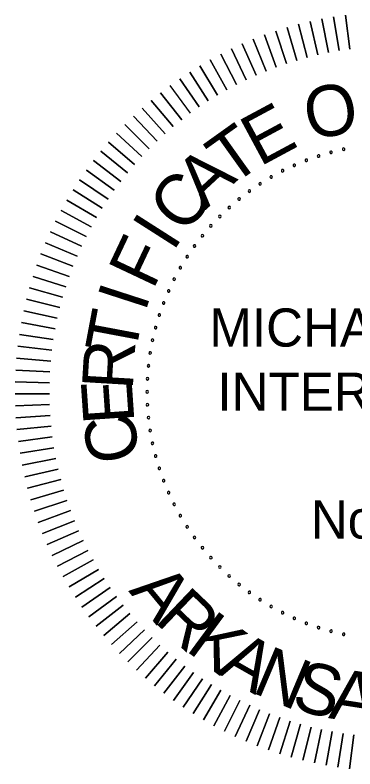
# Model space of a CAD drawing. Extents: x -4306 to 3843, y 131 to 8053.
# Drawn here: x 2723.6 to 2834.9, y 323.4 to 570.4 of the extents above; entities that cross this region are included whole.
import ezdxf

# ---------------------------------------------------------------- set-up
doc = ezdxf.new("R2010")
doc.units = 0
doc.layers.add('G-ANNO-TEXT', color=7, linetype='Continuous')

msp = doc.modelspace()

# ---------------------------------------------------------------- linework, layer by layer
at = {"layer": 'G-ANNO-TEXT'}
for points in [[(2822.74, 557.35), (2820.23, 568.28)], [(2820.23, 568.28), (2822.74, 557.35)], [(2826.22, 558.09), (2824.06, 569.1)], [(2824.06, 569.1), (2826.22, 558.09)], [(2829.72, 558.72), (2827.9, 569.79)], [(2827.9, 569.79), (2829.72, 558.72)], [(2833.24, 559.24), (2831.77, 570.36)], [(2831.77, 570.36), (2833.24, 559.24)], [(2815.86, 555.54), (2812.67, 566.3)], [(2812.67, 566.3), (2815.86, 555.54)], [(2819.29, 556.5), (2816.44, 567.35)], [(2816.44, 567.35), (2819.29, 556.5)], [(2809.11, 553.3), (2805.25, 563.84)], [(2805.25, 563.84), (2809.11, 553.3)], [(2812.47, 554.47), (2808.94, 565.13)], [(2808.94, 565.13), (2812.47, 554.47)], [(2802.51, 550.65), (2798, 560.92)], [(2798, 560.92), (2802.51, 550.65)], [(2805.79, 552.03), (2801.6, 562.44)], [(2801.6, 562.44), (2805.79, 552.03)], [(2799.28, 549.17), (2794.44, 559.29)], [(2794.44, 559.29), (2799.28, 549.17)], [(2792.96, 545.9), (2787.5, 555.71)], [(2787.5, 555.71), (2792.96, 545.9)], [(2796.09, 547.58), (2790.94, 557.55)], [(2790.94, 557.55), (2796.09, 547.58)], [(2789.88, 544.12), (2784.11, 553.75)], [(2784.11, 553.75), (2789.88, 544.12)], [(2786.86, 542.25), (2780.79, 551.69)], [(2780.79, 551.69), (2786.86, 542.25)], [(2783.9, 540.28), (2777.54, 549.52)], [(2777.54, 549.52), (2783.9, 540.28)], [(2781, 538.22), (2774.35, 547.26)], [(2778.17, 536.07), (2771.24, 544.89)], [(2771.24, 544.89), (2778.17, 536.07)], [(2775.4, 533.83), (2768.2, 542.43)], [(2768.2, 542.43), (2775.4, 533.83)], [(2772.71, 531.5), (2765.24, 539.88)], [(2765.24, 539.88), (2772.71, 531.5)], [(2770.09, 529.09), (2762.37, 537.23)], [(2762.37, 537.23), (2770.09, 529.09)], [(2767.55, 526.6), (2759.57, 534.49)], [(2759.57, 534.49), (2767.55, 526.6)], [(2765.09, 524.04), (2756.87, 531.67)], [(2756.87, 531.67), (2765.09, 524.04)], [(2762.71, 521.39), (2754.25, 528.77)], [(2754.25, 528.77), (2762.71, 521.39)], [(2760.42, 518.67), (2751.73, 525.78)], [(2751.73, 525.78), (2760.42, 518.67)], [(2758.21, 515.89), (2749.3, 522.72)], [(2749.3, 522.72), (2758.21, 515.89)], [(2756.09, 513.03), (2746.97, 519.58)], [(2746.97, 519.58), (2756.09, 513.03)], [(2754.06, 510.11), (2744.74, 516.37)], [(2744.74, 516.37), (2754.06, 510.11)], [(2752.13, 507.13), (2742.62, 513.09)], [(2742.62, 513.09), (2752.13, 507.13)], [(2750.28, 504.08), (2740.59, 509.74)], [(2740.59, 509.74), (2750.28, 504.08)], [(2748.54, 500.98), (2738.67, 506.33)], [(2738.67, 506.33), (2748.54, 500.98)], [(2746.89, 497.83), (2736.86, 502.87)], [(2736.86, 502.87), (2746.89, 497.83)], [(2745.35, 494.63), (2735.16, 499.35)], [(2735.16, 499.35), (2745.35, 494.63)], [(2743.9, 491.38), (2733.58, 495.78)], [(2733.58, 495.78), (2743.9, 491.38)], [(2742.56, 488.08), (2732.1, 492.16)], [(2732.1, 492.16), (2742.56, 488.08)], [(2741.32, 484.75), (2730.74, 488.49)], [(2730.74, 488.49), (2741.32, 484.75)], [(2740.18, 481.38), (2729.49, 484.79)], [(2729.49, 484.79), (2740.18, 481.38)], [(2739.16, 477.97), (2728.36, 481.04)], [(2728.36, 481.04), (2739.16, 477.97)], [(2738.24, 474.54), (2727.35, 477.27)], [(2727.35, 477.27), (2738.24, 474.54)], [(2737.43, 471.08), (2726.46, 473.46)], [(2726.46, 473.46), (2737.43, 471.08)], [(2736.73, 467.59), (2725.69, 469.63)], [(2725.69, 469.63), (2736.73, 467.59)], [(2736.13, 464.08), (2725.04, 465.78)], [(2725.04, 465.78), (2736.13, 464.08)], [(2735.65, 460.56), (2724.51, 461.9)], [(2724.51, 461.9), (2735.65, 460.56)], [(2735.28, 457.02), (2724.1, 458.01)], [(2724.1, 458.01), (2735.28, 457.02)], [(2735.02, 453.47), (2723.82, 454.11)], [(2723.82, 454.11), (2735.02, 453.47)], [(2734.87, 449.92), (2723.66, 450.21)], [(2723.66, 450.21), (2734.87, 449.92)], [(2734.84, 446.36), (2723.62, 446.3)], [(2723.62, 446.3), (2734.84, 446.36)], [(2734.91, 442.81), (2723.7, 442.39)], [(2723.7, 442.39), (2734.91, 442.81)], [(2735.1, 439.25), (2723.91, 438.49)], [(2723.91, 438.49), (2735.1, 439.25)], [(2735.4, 435.71), (2724.23, 434.59)], [(2724.23, 434.59), (2735.4, 435.71)], [(2735.81, 432.18), (2724.68, 430.71)], [(2724.68, 430.71), (2735.81, 432.18)], [(2736.33, 428.66), (2725.26, 426.84)], [(2725.26, 426.84), (2736.33, 428.66)], [(2736.96, 425.16), (2725.95, 422.99)], [(2725.95, 422.99), (2736.96, 425.16)], [(2737.7, 421.68), (2726.76, 419.17)], [(2726.76, 419.17), (2737.7, 421.68)], [(2738.55, 418.23), (2727.7, 415.37)], [(2727.7, 415.37), (2738.55, 418.23)], [(2739.51, 414.8), (2728.75, 411.61)], [(2728.75, 411.61), (2739.51, 414.8)], [(2740.57, 411.41), (2729.92, 407.88)], [(2729.92, 407.88), (2740.57, 411.41)], [(2741.75, 408.05), (2731.21, 404.19)], [(2731.21, 404.19), (2741.75, 408.05)], [(2743.02, 404.73), (2732.61, 400.54)], [(2732.61, 400.54), (2743.02, 404.73)], [(2744.4, 401.45), (2734.13, 396.94)], [(2734.13, 396.94), (2744.4, 401.45)], [(2745.88, 398.22), (2735.75, 393.38)], [(2735.75, 393.38), (2745.88, 398.22)], [(2747.46, 395.03), (2737.49, 389.88)], [(2737.49, 389.88), (2747.46, 395.03)], [(2749.15, 391.9), (2739.34, 386.44)], [(2739.34, 386.44), (2749.15, 391.9)], [(2750.93, 388.82), (2741.3, 383.05)], [(2741.3, 383.05), (2750.93, 388.82)], [(2752.8, 385.8), (2743.36, 379.73)], [(2743.36, 379.73), (2752.8, 385.8)], [(2754.77, 382.83), (2745.52, 376.47)], [(2745.52, 376.47), (2754.77, 382.83)], [(2756.83, 379.94), (2747.79, 373.29)], [(2747.79, 373.29), (2756.83, 379.94)], [(2758.98, 377.1), (2750.15, 370.18)], [(2750.15, 370.18), (2758.98, 377.1)], [(2761.22, 374.34), (2752.62, 367.14)], [(2752.62, 367.14), (2761.22, 374.34)], [(2763.55, 371.65), (2755.17, 364.18)], [(2755.17, 364.18), (2763.55, 371.65)], [(2765.96, 369.03), (2757.82, 361.3)], [(2757.82, 361.3), (2765.96, 369.03)], [(2768.45, 366.49), (2760.55, 358.51)], [(2760.55, 358.51), (2768.45, 366.49)], [(2771.01, 364.03), (2763.38, 355.81)], [(2763.38, 355.81), (2771.01, 364.03)], [(2766.28, 353.19), (2773.66, 361.65)], [(2773.66, 361.65), (2766.28, 353.19)], [(2769.27, 350.67), (2776.37, 359.36)], [(2776.37, 359.36), (2769.27, 350.67)], [(2772.33, 348.24), (2779.16, 357.15)], [(2779.16, 357.15), (2772.33, 348.24)], [(2775.47, 345.91), (2782.02, 355.03)], [(2782.02, 355.03), (2775.47, 345.91)], [(2778.68, 343.68), (2784.94, 353)], [(2784.94, 353), (2778.68, 343.68)], [(2781.96, 341.55), (2787.92, 351.06)], [(2787.92, 351.06), (2781.96, 341.55)], [(2785.31, 339.53), (2790.97, 349.22)], [(2790.97, 349.22), (2785.31, 339.53)], [(2788.71, 337.61), (2794.07, 347.48)], [(2794.07, 347.48), (2788.71, 337.61)], [(2792.18, 335.8), (2797.22, 345.83)], [(2797.22, 345.83), (2792.18, 335.8)], [(2795.7, 334.1), (2800.42, 344.28)], [(2800.42, 344.28), (2795.7, 334.1)], [(2799.27, 332.51), (2803.67, 342.84)], [(2803.67, 342.84), (2799.27, 332.51)], [(2802.89, 331.04), (2806.96, 341.49)], [(2806.96, 341.49), (2802.89, 331.04)], [(2806.56, 329.68), (2810.3, 340.26)], [(2810.3, 340.26), (2806.56, 329.68)], [(2810.26, 328.43), (2813.67, 339.12)], [(2813.67, 339.12), (2810.26, 328.43)], [(2814, 327.3), (2817.07, 338.1)], [(2817.07, 338.1), (2814, 327.3)], [(2817.78, 326.29), (2820.51, 337.18)], [(2820.51, 337.18), (2817.78, 326.29)], [(2821.59, 325.4), (2823.97, 336.37)], [(2823.97, 336.37), (2821.59, 325.4)], [(2825.42, 324.63), (2827.46, 335.66)], [(2827.46, 335.66), (2825.42, 324.63)], [(2829.27, 323.98), (2830.97, 335.07)], [(2830.97, 335.07), (2829.27, 323.98)], [(2833.15, 323.45), (2834.49, 334.59)], [(2834.49, 334.59), (2833.15, 323.45)]]:
    msp.add_lwpolyline(points, dxfattribs=at)
for centre, start, end in [((2831.17, 526.43), 12, 192), ((2831.17, 526.43), 192, 12), ((2822.96, 524.23), 18, 198), ((2822.96, 524.23), 198, 18), ((2827.04, 525.44), 15, 195), ((2827.04, 525.44), 195, 15), ((2815.02, 521.19), 24, 204), ((2815.02, 521.19), 204, 24), ((2818.95, 522.81), 21, 201), ((2818.95, 522.81), 201, 21), ((2811.18, 519.36), 27, 207), ((2811.18, 519.36), 207, 27), ((2807.45, 517.33), 30, 210), ((2807.45, 517.33), 210, 30), ((2803.82, 515.11), 33, 213), ((2803.82, 515.11), 213, 33), ((2800.32, 512.7), 36, 216), ((2800.32, 512.7), 216, 36), ((2796.95, 510.11), 39, 219), ((2796.95, 510.11), 219, 39), ((2793.71, 507.35), 42, 222), ((2793.71, 507.35), 222, 42), ((2790.63, 504.42), 45, 225), ((2790.63, 504.42), 225, 45), ((2787.7, 501.34), 48, 228), ((2787.7, 501.34), 228, 48), ((2784.94, 498.1), 51, 231), ((2784.94, 498.1), 231, 51), ((2782.35, 494.73), 54, 234), ((2782.35, 494.73), 234, 54), ((2779.94, 491.23), 57, 237), ((2779.94, 491.23), 237, 57), ((2777.72, 487.6), 60, 240), ((2777.72, 487.6), 240, 60), ((2775.69, 483.86), 63, 243), ((2775.69, 483.86), 243, 63), ((2773.86, 480.03), 66, 246), ((2773.86, 480.03), 246, 66), ((2772.23, 476.1), 69, 249), ((2772.23, 476.1), 249, 69), ((2770.82, 472.09), 72, 252), ((2770.82, 472.09), 252, 72), ((2769.61, 468.01), 75, 255), ((2769.61, 468.01), 255, 75), ((2768.62, 463.88), 78, 258), ((2768.62, 463.88), 258, 78), ((2767.84, 459.7), 81, 261), ((2767.84, 459.7), 261, 81), ((2767.29, 455.48), 84, 264), ((2767.29, 455.48), 264, 84), ((2766.95, 451.24), 87, 267), ((2766.95, 451.24), 267, 87), ((2766.84, 446.99), 90, 270), ((2766.84, 446.99), 270, 90), ((2766.95, 442.74), 93, 273), ((2766.95, 442.74), 273, 93), ((2767.29, 438.5), 96, 276), ((2767.29, 438.5), 276, 96), ((2767.84, 434.29), 99, 279), ((2767.84, 434.29), 279, 99), ((2768.62, 430.11), 102, 282), ((2768.62, 430.11), 282, 102), ((2769.61, 425.97), 105, 285), ((2769.61, 425.97), 285, 105), ((2770.82, 421.9), 108, 288), ((2770.82, 421.9), 288, 108), ((2772.23, 417.89), 111, 291), ((2772.23, 417.89), 291, 111), ((2773.86, 413.96), 114, 294), ((2773.86, 413.96), 294, 114), ((2775.69, 410.12), 117, 297), ((2775.69, 410.12), 297, 117), ((2777.72, 406.39), 120, 300), ((2777.72, 406.39), 300, 120), ((2779.94, 402.76), 123, 303), ((2779.94, 402.76), 303, 123), ((2782.35, 399.26), 126, 306), ((2782.35, 399.26), 306, 126), ((2784.94, 395.88), 129, 309), ((2784.94, 395.88), 309, 129), ((2787.7, 392.65), 132, 312), ((2787.7, 392.65), 312, 132), ((2790.63, 389.57), 135, 315), ((2790.63, 389.57), 315, 135), ((2793.71, 386.64), 138, 318), ((2793.71, 386.64), 318, 138), ((2796.95, 383.88), 141, 321), ((2796.95, 383.88), 321, 141), ((2800.32, 381.29), 144, 324), ((2800.32, 381.29), 324, 144), ((2803.82, 378.88), 147, 327), ((2803.82, 378.88), 327, 147), ((2807.45, 376.66), 150, 330), ((2807.45, 376.66), 330, 150), ((2811.18, 374.63), 153, 333), ((2811.18, 374.63), 333, 153), ((2815.02, 372.8), 156, 336), ((2815.02, 372.8), 336, 156), ((2818.95, 371.17), 159, 339), ((2818.95, 371.17), 339, 159), ((2822.96, 369.75), 162, 342), ((2822.96, 369.75), 342, 162), ((2827.04, 368.55), 165, 345), ((2827.04, 368.55), 345, 165), ((2831.17, 367.55), 348, 168), ((2831.17, 367.55), 168, 348)]:
    msp.add_arc(centre, 0.417, start, end, dxfattribs=at)

# ---------------------------------------------------------------- texts
for s, rotation, p in [('O', 10.7295, (2819.9, 529.32)), ('E', 28.279, (2803.71, 520.59)), ('T', 35.5725, (2794.41, 514.13)), ('A', 42.8659, (2785.94, 506.43)), ('C', 50.1594, (2778.93, 498.1)), ('I', 57.4529, (2775.31, 492.53)), ('F', 64.7464, (2768.77, 480.07)), ('I', 72.0398, (2766.19, 472.74)), ('T', 79.3333, (2762.87, 458.38)), ('R', 86.6268, (2762.11, 447.36)), ('E', 93.9203, (2762.72, 436.95)), ('C', 101.2137, (2764.86, 425.36)), ('A', 309.5859, (2760.59, 381.73)), ('R', 316.3356, (2768.87, 371.9)), ('K', 323.6428, (2779.06, 362.44)), ('A', 330.3925, (2789.48, 354.92)), ('N', 337.1422, (2800.71, 348.67)), ('S', 344.4494, (2813.6, 343.45)), ('A', 351.1991, (2826, 340.11))]:
    msp.add_text(s, height=16.67, rotation=rotation, dxfattribs=at).set_placement(p)
for s, height, p in [('MICHAEL BAKER', 12.5016, (2787.23, 461.77)), (' INTERNATIONAL', 12.5016, (2785.22, 440.75)), (' No. 1126', 12.502, (2815.79, 398.89))]:
    msp.add_text(s, height=height, dxfattribs=at).set_placement(p)

doc.saveas('drawing.dxf')
